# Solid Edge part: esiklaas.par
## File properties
Author: Türk
Template: iso part.par
Last saved by: Türk
Revision: 9
Application: Solid Edge
Accuracy: 0,990
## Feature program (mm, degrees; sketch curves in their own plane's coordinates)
base feature "unnamed BaseFeature 1"
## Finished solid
Body 1: solid body, 78 faces, 194 edges, 126 vertices, 5 separate solids.
  Faces by surface: spline 40, blend 14, plane 12, offset 10, swept 2
  Edges by curve: curve on surface 77, intersection 72, spline 26, line 16, ellipse 2, circle 1
Body 2: sheet body, 14 faces, 51 edges, 42 vertices.
  Faces by surface: spline 8, plane 4, swept 2
  Edges by curve: spline 25, curve on surface 10, line 8, intersection 6, ellipse 2
Body 3: sheet body, 1 face, 4 edges, 4 vertices.
  Faces by surface: swept 1
  Edges by curve: ellipse 2, line 2
Body 4: sheet body, 3 faces, 10 edges, 8 vertices.
  Faces by surface: plane 2, swept 1
  Edges by curve: line 8, ellipse 2
Bounding box of the edges (mm; curved faces can reach further): 1299.877 x 364.075 x 525.461, from (-649.8772, 809.9999, 425.6357) to (650, 1174.0746, 951.0966).
Planar faces by outward normal: oblique 12
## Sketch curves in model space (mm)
spline (599.9685, 865.0119, 450) -> (639.4536, 897.9177, 450) -> (649.5083, 960.8303, 450)
spline (377.4735, 831.7771, 450) -> (488.7213, 846.5033, 450) -> (599.9685, 865.0119, 450)
arc centre (-626.0744, 981.4887, 547.899) radius 11.1246 from (-637.0148, 981.9209, 549.868) through (-636.9541, 981.9864, 550.1662) to (-636.8849, 982.0515, 550.4626)
line (-637.0219, 981.9126, 549.8301) -> (-637.0148, 981.9209, 549.868)
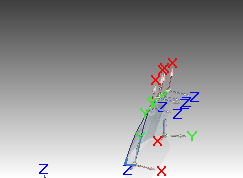
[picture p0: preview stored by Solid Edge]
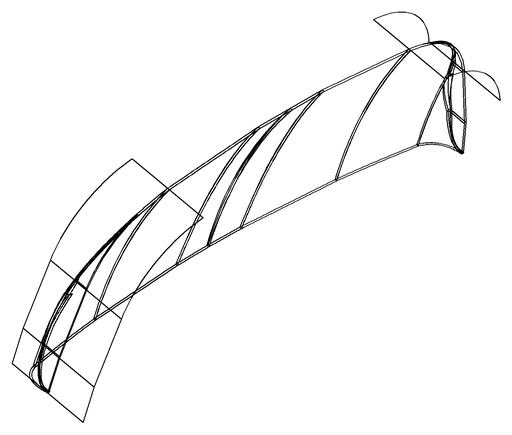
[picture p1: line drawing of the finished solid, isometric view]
